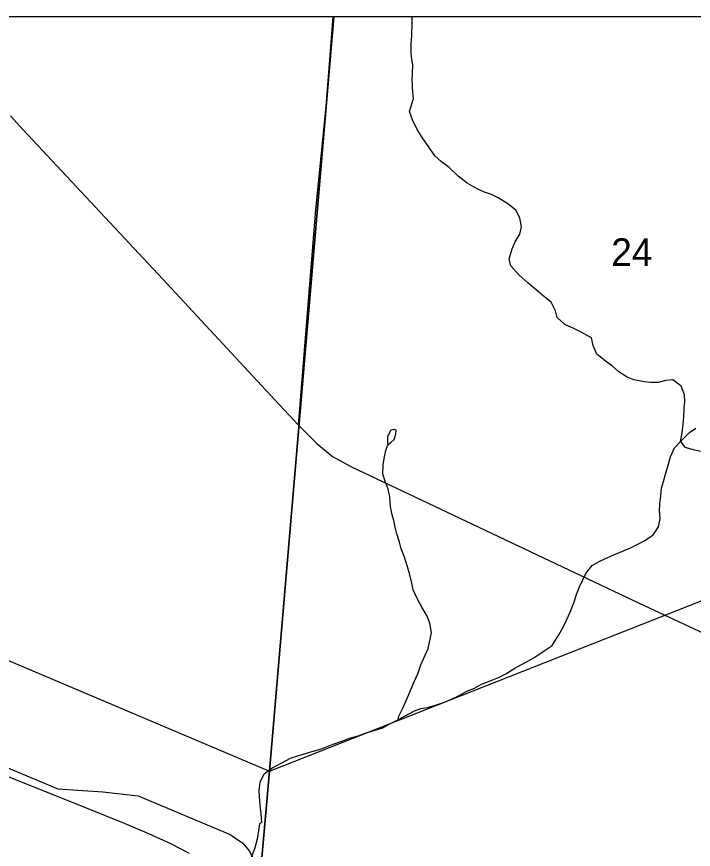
# Model space of a CAD drawing. Extents: x 0 to 34, y 0 to 22.
# Drawn here: x 11.83 to 12.852, y 18.979 to 20.236 of the extents above; entities that cross this region are included whole.
import ezdxf

# ---------------------------------------------------------------- set-up
doc = ezdxf.new("R2010")
doc.units = 0
for name, color, linetype in [('GM_X_City_Street', 7, 'Continuous'), ('GM_X_County_Road', 7, 'Continuous'), ('GM_X_Minor_River', 7, 'Continuous'), ('GM_X_Rail_Line', 7, 'Continuous'), ('GM_X_Section', 7, 'Continuous'), ('GM_X_Section_Text', 7, 'Continuous'), ('GM_X_Unincorporated', 7, 'Continuous'), ('SC_Scratch1', 7, 'Continuous'), ('SH_Border', 7, 'Continuous'), ('SH_Cut_Line', 7, 'Continuous')]:
    doc.layers.add(name, color=color, linetype=linetype)

msp = doc.modelspace()

# ---------------------------------------------------------------- linework, layer by layer
at = {"layer": 'GM_X_City_Street'}
msp.add_lwpolyline([(12.256, 19.6191), (12.2821, 19.945), (12.2976, 20.1005), (12.308, 20.2361)], dxfattribs=at)
at = {"layer": 'GM_X_County_Road'}
for points in [[(11.8207, 20.0865), (11.84, 20.0652), (12.0509, 19.8397), (12.2197, 19.6578), (12.256, 19.6191), (12.2833, 19.5915), (12.307, 19.572), (12.3357, 19.5561), (12.7702, 19.3503), (12.8677, 19.3049)], [(11.6265, 19.1808), (11.6359, 19.1771), (11.8921, 19.07), (11.96, 19.0652), (12.0135, 19.0593), (12.1528, 19.0009), (12.1719, 18.9878), (12.1811, 18.9765), (12.1886, 18.9616), (12.1907, 18.9497), (12.1921, 18.9342)]]:
    msp.add_lwpolyline(points, dxfattribs=at)
at = {"layer": 'GM_X_Minor_River'}
for points in [[(12.4236, 20.0927), (12.4294, 20.1125), (12.4285, 20.1227), (12.4279, 20.1288), (12.428, 20.1345), (12.4277, 20.139), (12.4283, 20.1633), (12.4277, 20.1682), (12.4263, 20.1758), (12.4261, 20.1808), (12.4259, 20.188), (12.426, 20.1955), (12.4265, 20.2004), (12.4271, 20.2076), (12.4275, 20.2266), (12.4274, 20.2345), (12.4273, 20.2361)], [(12.8329, 19.5946), (12.8351, 19.6078), (12.837, 19.62), (12.8377, 19.6317), (12.8384, 19.6443), (12.8391, 19.6549), (12.839, 19.6652), (12.8337, 19.6783), (12.821, 19.6874), (12.8107, 19.6865), (12.7988, 19.6834), (12.7874, 19.6837), (12.778, 19.6847), (12.7621, 19.6878), (12.7523, 19.6915), (12.7396, 19.6998), (12.73, 19.7081), (12.7195, 19.7156), (12.7065, 19.7262), (12.7008, 19.7393), (12.6985, 19.7512), (12.6827, 19.7596), (12.6726, 19.7648), (12.658, 19.7713), (12.6465, 19.7819), (12.6441, 19.7918), (12.6376, 19.805), (12.6253, 19.8144), (12.6146, 19.8235), (12.6023, 19.8341), (12.589, 19.8458), (12.5764, 19.8599), (12.574, 19.8702), (12.5787, 19.8857), (12.5831, 19.8959), (12.5903, 19.9075), (12.5925, 19.9188), (12.5902, 19.9322), (12.5841, 19.9438), (12.5718, 19.9536), (12.5572, 19.9624), (12.5475, 19.9676), (12.535, 19.9717), (12.5245, 19.9766), (12.5107, 19.9846), (12.4969, 19.9952), (12.4832, 20.0082), (12.472, 20.0168), (12.4616, 20.0259), (12.4522, 20.0402), (12.4434, 20.0519), (12.435, 20.0658), (12.4278, 20.0801), (12.4236, 20.0927)], [(12.2005, 19.0191), (12.1994, 19.0321), (12.1979, 19.0458), (12.1971, 19.058), (12.1966, 19.068), (12.1977, 19.0801), (12.2041, 19.0925), (12.2157, 19.1009), (12.2304, 19.1093), (12.2439, 19.1161), (12.2562, 19.1204), (12.2665, 19.1231), (12.278, 19.1266), (12.2903, 19.1305), (12.3083, 19.1372), (12.3229, 19.1422), (12.3329, 19.1465), (12.3459, 19.1499), (12.3567, 19.1542), (12.3666, 19.157), (12.3831, 19.1622), (12.3935, 19.168), (12.4066, 19.1745), (12.4178, 19.1807), (12.431, 19.1876), (12.4405, 19.1911), (12.4505, 19.1928), (12.4643, 19.197), (12.475, 19.2001), (12.4858, 19.2047), (12.4993, 19.2116), (12.5101, 19.2174), (12.5216, 19.222), (12.5324, 19.2278), (12.5451, 19.2332), (12.5581, 19.2382), (12.5689, 19.2436), (12.5825, 19.252), (12.5925, 19.2578), (12.6021, 19.2625), (12.6126, 19.2687), (12.6269, 19.2782), (12.6389, 19.2866), (12.6489, 19.3023), (12.6556, 19.3139), (12.6605, 19.3245), (12.6661, 19.3365), (12.6715, 19.3508), (12.6764, 19.3651), (12.6801, 19.3749), (12.6898, 19.3952), (12.6993, 19.4071), (12.7101, 19.4133), (12.7197, 19.418), (12.7312, 19.423), (12.7443, 19.4284), (12.7574, 19.4341), (12.7705, 19.4402), (12.7801, 19.4453), (12.7921, 19.4541), (12.7997, 19.4657), (12.8019, 19.4782), (12.8011, 19.49), (12.8014, 19.4999), (12.8029, 19.512), (12.8043, 19.5238), (12.8069, 19.534), (12.8102, 19.5453), (12.814, 19.5589), (12.8178, 19.5714), (12.8239, 19.5849), (12.8329, 19.5946), (12.8462, 19.6079), (12.8559, 19.6145)], [(12.3907, 19.5894), (12.3958, 19.5934), (12.4001, 19.5975), (12.4029, 19.6054), (12.4035, 19.6115), (12.4005, 19.6127), (12.3951, 19.6117), (12.3903, 19.602)], [(12.3903, 19.602), (12.3904, 19.5932), (12.3907, 19.5894)], [(12.8329, 19.5946), (12.8391, 19.586), (12.8519, 19.5823), (12.8629, 19.5797)], [(12.4066, 19.1745), (12.4068, 19.1787), (12.4136, 19.1919), (12.4189, 19.2043), (12.4238, 19.2159), (12.4302, 19.2306), (12.4359, 19.2434), (12.4405, 19.2573), (12.4473, 19.272), (12.4514, 19.2818), (12.4548, 19.2962), (12.4566, 19.306), (12.454, 19.3202), (12.4501, 19.3305), (12.4421, 19.3444), (12.4352, 19.3572), (12.4288, 19.3703), (12.4268, 19.3806), (12.4237, 19.3929), (12.4202, 19.4052), (12.4157, 19.4198), (12.4111, 19.4324), (12.4083, 19.4424), (12.4041, 19.4551), (12.4017, 19.465), (12.3997, 19.475), (12.397, 19.4857), (12.3946, 19.4964), (12.3935, 19.5105), (12.3911, 19.5224), (12.3862, 19.5359), (12.3834, 19.5454), (12.3838, 19.5591), (12.3852, 19.5686), (12.3878, 19.5811)], [(12.3878, 19.5811), (12.3907, 19.5894)], [(12.2005, 19.0191), (12.1967, 19.017), (12.1953, 19.0071), (12.1934, 18.9938), (12.19, 18.9806), (12.1847, 18.9674), (12.1786, 18.9535), (12.1718, 18.943), (12.1643, 18.9307), (12.1597, 18.9167), (12.1598, 18.9072), (12.1618, 18.8957), (12.1602, 18.8655)]]:
    msp.add_lwpolyline(points, dxfattribs=at)
at = {"layer": 'GM_X_Rail_Line'}
msp.add_lwpolyline([(12.0911, 18.9725), (12.0628, 18.9868), (12.0297, 19.0018), (11.9928, 19.0174), (11.9069, 19.0522), (11.8401, 19.0788), (11.7591, 19.1115)], dxfattribs=at)
at = {"layer": 'GM_X_Section'}
for points in [[(11.2353, 19.5105), (12.2122, 19.0964), (12.129, 18.1574), (11.148, 18.4749)], [(12.2122, 19.0964), (13.2088, 19.4896), (13.1359, 18.4571), (12.129, 18.1574)]]:
    msp.add_lwpolyline(points, close=True, dxfattribs=at)
at = {"layer": 'GM_X_Unincorporated'}
for points in [[(12.3092, 20.2361), (11.3044, 20.2361), (11.2353, 19.5105), (12.2122, 19.0964)], [(13.2677, 20.2361), (12.3092, 20.2361), (12.2122, 19.0964), (13.2088, 19.4896)]]:
    msp.add_lwpolyline(points, close=True, dxfattribs=at)
at = {"layer": 'SC_Scratch1'}
msp.add_lwpolyline([(14.0411, 15.8502), (14.0483, 15.9927), (14.1092, 16.7637), (14.1287, 17.0041), (14.1791, 17.6233), (14.1894, 17.7492), (14.1911, 17.7706), (14.3035, 19.1497), (14.3921, 20.0277), (14.3942, 20.0656), (14.3998, 20.147), (14.4075, 20.2361), (9.6073, 20.2361)], dxfattribs=at)
at = {"layer": 'SH_Border'}
msp.add_lwpolyline([(9.3, 20.2361), (9.3, 13.4361), (16.1, 13.4361), (16.1, 20.2361)], close=True, dxfattribs=at)
at = {"layer": 'SH_Cut_Line'}
msp.add_lwpolyline([(16.1, 14.8738), (16.1, 20.2361), (9.3, 20.2361), (9.3, 15.5386)], dxfattribs=at)

# ---------------------------------------------------------------- texts
at = {"layer": 'GM_X_Section_Text'}
msp.add_text('24', height=0.04186, rotation=0, dxfattribs=at).set_placement((12.7282, 19.8595))

doc.saveas('drawing.dxf')
